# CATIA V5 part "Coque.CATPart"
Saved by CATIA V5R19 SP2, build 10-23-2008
Part number: Coque
Bounding box of the stored display mesh (mm): x 0 to 3, y -8 to 82, z -11.547 to 7.453
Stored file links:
  G:\EU_thinkMotion\CFAO_2010\MMS_groupe3\MMS_groupe3\A reprendre\lletoffe\lletoffe_Thinkmotion_CFAO\Modèle Catia\Coque.CATPart
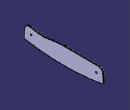
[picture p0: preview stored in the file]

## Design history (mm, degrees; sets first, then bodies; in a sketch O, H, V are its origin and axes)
Parameters
  Epaisseur = 3 mm
Set1
  Point1: (0, 0, 0)
  Point2: (0, 74, 0)
  Point3: (1, 74, 0)
  Point4: (1, 0, 0)
  Line1: type PtPt, FirstPoint Point1, SecondPoint Point4, Start 10, End 10
  Line2: type PtPt, FirstPoint Point2, SecondPoint Point3, Start 10, End 10
  Plane1: type Offset, RefPlane yz-plane, Offset 3 {= Epaisseur}
  Sketch1 on yz-plane, origin (0, 0, 0), H (0, 1, 0), V (0, 0, 1)
    arc A1 centre (-2.5441, 2.7473) radius 4.5 from (-1.2681, 7.0627) to (-6.9379, 3.7193) ccw
    arc A2 centre (37, -6) radius 45 from (-6.9379, 3.7193) to (-8, -6) ccw
    arc A3 centre (-6.25, -6) radius 1.75 from (-8, -6) to (-6.5549, -7.7232) ccw
    point P1 (-6.25, -6)
    construction line L1 through (0, -4.0671) direction (0, 1)
    point P3 (37, -6)
    arc A4 centre (12.9096, 55.0105) radius 50 from (-1.2681, 7.0627) to (22.9472, 6.0284) ccw
    arc A5 centre (37, 238.4535) radius 250 from (-6.5549, -7.7232) to (37, -11.5465) ccw
    point P5 (37, -62.5465)
    construction line L2 through (-2.0871, 0) direction (1, 0)
    arc A6 centre (37, -62.5465) radius 70 from (37, 7.4535) to (22.9472, 6.0284) ccw
    point P6 (37, 7.4535)
    point P7 (37, -11.5465)
    point P8 (12.9096, 55.0105)
    point P11 (-6.9379, 3.7193)
    point P12 (-6.5549, -7.7232)
    point P13 (-8, -6)
    reference projected point E1 (0, 0) from Line1
    reference projected point E2 (0, 0) from Line1
    axis line L3 (37, 7.4535) -> (37, -11.5465)
    point P18 (37, 7.4535)
    point P19 (80.9379, 3.7193)
    point P20 (82, -6)
    arc A7 centre (37, -6) radius 45 from (80.9379, 3.7193) to (82, -6) cw
    point P22 (80.5549, -7.7232)
    arc A8 centre (80.25, -6) radius 1.75 from (82, -6) to (80.5549, -7.7232) cw
    point P24 (37, -11.5465)
    arc A9 centre (37, 238.4535) radius 250 from (80.5549, -7.7232) to (37, -11.5465) cw
    arc A10 centre (76.5441, 2.7473) radius 4.5 from (80.9379, 3.7193) to (76.5675, 7.2473) ccw
    line L4 (37, 7.4535) -> (76.5675, 7.2473)
    radius A1 = 4.5
    radius A3 = 1.75
    radius A4 = 50
    radius A5 = 250
    radius A2 = 45
    distance P1 L1 = 6.25
    radius A6 = 70
    distance L2 P1 = 6
    distance P8 L1 = 12.9096
    distance L3 L1 = 37
    length L3 = 19
    distance L2 P8 = 55.0105
    radius A10 = 4.5
    tangency: A2 A1, A3 A2, A4 A1, A5 A3, A6 A4, A7 A10, L4 A10
    coincidence: L1 E1, L2 E2, P5 L3, P3 L3, P6 P18, P7 P24
    perpendicularity: L1 L2
    horizontal: L2 H
    vertical: L3 V
    symmetry: P6 P18 L3, P11 P19 L3, P13 P20 L3, A2 A7 L3, P12 P22 L3, A3 A8 L3, P7 P24 L3, A5 A9 L3
Body1 (main body)
  Pad1: profile Sketch1, direction (1, 0, 0), up to Plane1
  Sketch2 on end face of Pad1, origin (3, 0, 0), H (0, 1, 0), V (0, 0, 1)
    circle A1 centre (74, 0) radius 1
    circle A2 centre (0, 0) radius 1
    reference projected point E1 (0, 0) from Line1
    reference projected point E2 (74, 0) from Line2
    radius A1 = 1
    radius A2 = 1
    concentricity: A2 E1, A1 E2
  Pocket1: profile Sketch2, direction (-1, 0, 0), length 1.5 {= Epaisseur /2}
  Fillet1: radius 2, on start face of Pad1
